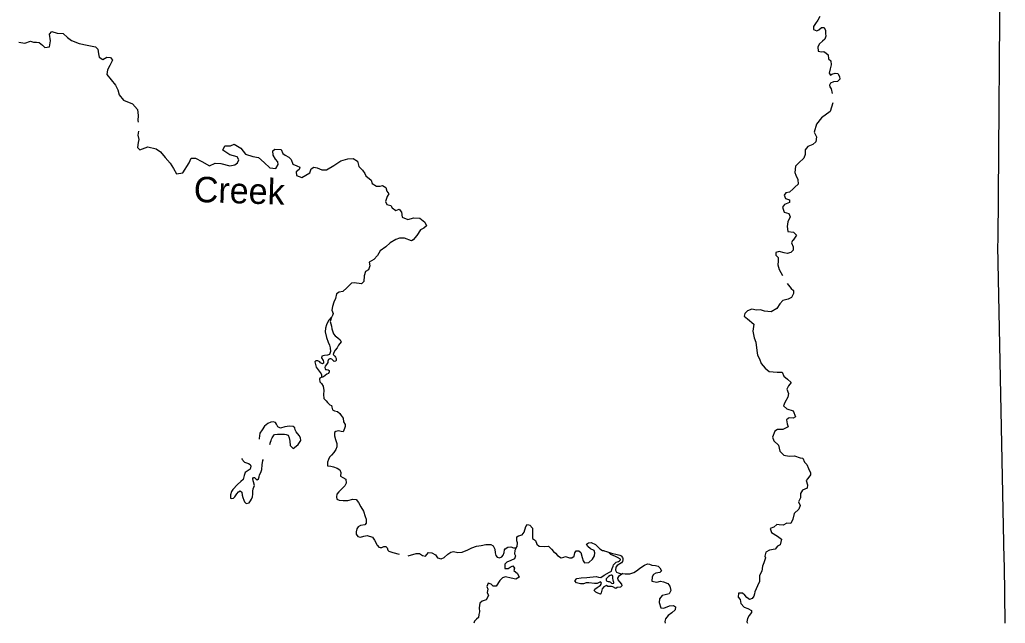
# Model space of a CAD drawing. Extents: x -492261 to -432772, y 1441225 to 1452922.
# Drawn here: x -459662.3 to -459457.9, y 1451554.7 to 1451679.8 of the extents above; entities that cross this region are included whole.
import ezdxf

# ---------------------------------------------------------------- set-up
doc = ezdxf.new("R2010")
doc.units = 0
doc.layers.add('Default', color=7, linetype='Continuous')

msp = doc.modelspace()

# ---------------------------------------------------------------- linework, layer by layer
at = {"layer": 'Default'}
for points in [[(-459457.93, 1451554.74), (-459458.06, 1451566.69), (-459458.15, 1451568.06), (-459459.48, 1451632.91), (-459459.37, 1451634.11), (-459458.89, 1451698.33), (-459458.81, 1451699.68), (-459458.3, 1451765.23), (-459457.92, 1451832.41), (-459458.17, 1451883.95)], [(-459496.34, 1451680.48), (-459496.75, 1451679.69), (-459497.29, 1451679.04), (-459497.69, 1451678.39), (-459497.7, 1451677.75), (-459497, 1451677.53), (-459496.56, 1451677.74), (-459496.04, 1451678.18), (-459495.46, 1451678.17), (-459495.16, 1451677.61), (-459495.22, 1451676.96), (-459495.13, 1451676.38), (-459495.35, 1451675.81), (-459495.81, 1451675.36), (-459496.41, 1451674.78), (-459496.79, 1451674.2), (-459496.7, 1451673.31), (-459496.02, 1451673.17), (-459495.52, 1451673.21), (-459495.05, 1451672.87), (-459494.61, 1451672.52), (-459494.58, 1451671.73), (-459494.07, 1451671.31), (-459494.05, 1451670.47), (-459494.25, 1451669.63), (-459494.41, 1451668.76), (-459494.14, 1451668.29), (-459493.86, 1451668.5), (-459493.2, 1451668.75), (-459492.66, 1451668.66), (-459492.26, 1451668.07), (-459492.22, 1451667.49), (-459492.68, 1451666.98), (-459493.51, 1451666.91), (-459494.18, 1451666.66), (-459494.37, 1451666.24), (-459494.31, 1451665.88), (-459494.05, 1451665.51), (-459493.83, 1451664.49)], [(-459662.43, 1451675.18), (-459661.19, 1451674.96), (-459659.99, 1451675.36), (-459659.39, 1451675.18), (-459658.76, 1451675.14), (-459658.22, 1451675.06), (-459657.53, 1451674.51), (-459657.02, 1451674.05), (-459656.07, 1451674.22), (-459655.88, 1451675.42), (-459656.06, 1451676.8), (-459655.58, 1451677.39), (-459654.46, 1451677.03), (-459653.23, 1451676.93), (-459652.38, 1451676.16), (-459651.49, 1451675.5), (-459649.93, 1451674.85), (-459648.26, 1451674.54), (-459646.56, 1451674.22), (-459646.06, 1451673.7), (-459645.95, 1451672.77), (-459645.81, 1451672.03), (-459645.02, 1451671.54), (-459644.16, 1451672.07), (-459643.44, 1451671.96), (-459643, 1451671.43), (-459643.59, 1451670.32), (-459644.06, 1451669.44), (-459644.19, 1451668.45), (-459643.28, 1451667.32), (-459642.43, 1451666.24), (-459641.9, 1451665.3), (-459641.62, 1451664.23), (-459640.75, 1451663.17), (-459638.89, 1451662.36), (-459637.85, 1451661.21), (-459637.69, 1451659.96), (-459637.77, 1451658.96), (-459637.73, 1451658.58)], [(-459493.7, 1451662.61), (-459494.21, 1451660.81), (-459496.01, 1451659.45), (-459497.04, 1451658.14), (-459497.51, 1451656.52), (-459497.03, 1451655.57), (-459497.2, 1451654.52), (-459497.81, 1451653.94), (-459498.83, 1451653.54), (-459499.42, 1451652.85), (-459499.41, 1451651.89), (-459499.7, 1451651.15), (-459500.74, 1451650.16), (-459501.4, 1451649.46), (-459501.56, 1451648.18), (-459501.35, 1451647.58), (-459500.95, 1451646.73), (-459500.85, 1451645.7), (-459501.58, 1451645.14), (-459501.9, 1451644.79), (-459502.64, 1451644.06), (-459503.41, 1451643.91), (-459503.74, 1451643.48), (-459503.47, 1451642.75), (-459502.66, 1451642.49), (-459502.66, 1451641.95), (-459503.7, 1451641.54), (-459504.1, 1451640.97), (-459503.77, 1451639.92), (-459502.8, 1451639.64), (-459502.54, 1451638.98), (-459502.97, 1451637.91), (-459503.12, 1451636.99), (-459503.02, 1451635.92), (-459501.83, 1451635.78), (-459501.24, 1451635.15), (-459501.88, 1451634.12), (-459502.01, 1451634.04), (-459502.22, 1451633.59), (-459501.9, 1451632.73), (-459501.88, 1451632.09), (-459502.36, 1451631.56), (-459503.13, 1451631.39), (-459503.73, 1451631.48), (-459504.77, 1451631.81), (-459505.49, 1451631.55), (-459505.52, 1451631.01), (-459505, 1451630.55), (-459505.04, 1451629.81), (-459505.08, 1451629), (-459504.77, 1451628.03), (-459504.12, 1451626.79)], [(-459637.66, 1451656.7), (-459637.79, 1451655.92), (-459637.55, 1451655.01), (-459637.7, 1451654.34), (-459637.81, 1451653.3), (-459637.33, 1451652.86), (-459635.68, 1451653.44), (-459634, 1451653.06), (-459633.09, 1451652.44), (-459632.12, 1451651.26), (-459631.08, 1451650.06), (-459630.39, 1451648.99), (-459629.76, 1451647.89), (-459628.43, 1451648.06), (-459627.1, 1451650.18), (-459626.69, 1451651.1), (-459625.78, 1451651.13), (-459624.5, 1451650.46), (-459622.88, 1451649.54), (-459621.72, 1451650.08), (-459620.55, 1451650), (-459618.68, 1451649.51), (-459617.69, 1451649.76), (-459617.08, 1451650.16), (-459616.84, 1451650.8), (-459617.15, 1451651.37), (-459618.7, 1451651.83), (-459620.13, 1451652.81), (-459619.76, 1451653.66), (-459618.57, 1451653.68), (-459617.77, 1451654.01), (-459616.42, 1451653.2), (-459615.43, 1451651.98), (-459613.95, 1451651.46), (-459612.78, 1451651.26), (-459611.55, 1451650.24), (-459610.41, 1451649.11), (-459609.13, 1451648.96), (-459608.65, 1451649.84), (-459608.76, 1451650.37)], [(-459608.76, 1451650.37), (-459609.22, 1451650.94), (-459609.73, 1451651.74), (-459609.8, 1451652.62), (-459609.36, 1451653.01), (-459608.08, 1451652.94), (-459607.73, 1451652.11), (-459607.22, 1451651.74), (-459606.49, 1451651.33), (-459606, 1451650.82), (-459605.63, 1451649.86), (-459604.82, 1451649.56), (-459604.16, 1451649.28), (-459604.33, 1451648.77), (-459604.94, 1451648.27), (-459604.84, 1451647.56), (-459603.76, 1451647.09), (-459602.11, 1451648.1), (-459601.81, 1451648.89), (-459601.28, 1451649.23), (-459600.59, 1451649.13), (-459599.61, 1451648.72), (-459598.62, 1451648.69), (-459597.16, 1451649.61), (-459595.67, 1451650.54), (-459594.25, 1451650.96), (-459593.15, 1451651.04), (-459592.24, 1451650.48), (-459591.93, 1451649.42), (-459591.19, 1451648.61), (-459590.69, 1451647.92), (-459590.5, 1451647.45), (-459589.42, 1451646.59), (-459589.16, 1451645.86), (-459588.26, 1451645.34), (-459587.52, 1451645.32), (-459587.07, 1451645.47), (-459586.33, 1451645.02), (-459586.17, 1451644.31), (-459585.72, 1451643.76), (-459586.06, 1451643.16), (-459586.44, 1451642.12), (-459586.14, 1451641.54), (-459585.3, 1451641.34), (-459585.07, 1451640.8), (-459584.3, 1451640.25), (-459583.57, 1451640.52), (-459583.09, 1451639.94), (-459582.98, 1451638.93), (-459581.81, 1451638.39), (-459580.55, 1451638.77), (-459579.27, 1451638.66), (-459578.29, 1451637.84), (-459577.92, 1451637.11), (-459578.47, 1451636.63), (-459579.18, 1451636.24), (-459579.95, 1451635.09), (-459580.65, 1451634.23), (-459581.05, 1451633.98), (-459582.47, 1451634.57), (-459583.52, 1451634.54), (-459584.31, 1451634.28), (-459585.44, 1451633.58), (-459586.37, 1451632.73), (-459587.51, 1451631.95), (-459588.1, 1451630.94), (-459588.86, 1451630.15), (-459589.8, 1451629.55), (-459589.67, 1451628.78), (-459589.92, 1451627.98), (-459590.54, 1451627.64), (-459590.83, 1451626.76), (-459590.88, 1451625.59), (-459591.42, 1451625.09), (-459592.92, 1451625.29), (-459593.48, 1451625.2), (-459594.43, 1451624.25), (-459595.23, 1451623.51), (-459596.05, 1451623.38), (-459596.57, 1451623), (-459596.81, 1451622.03), (-459597.1, 1451621.28), (-459597.39, 1451620.35), (-459597.53, 1451619.62), (-459597.28, 1451618.91), (-459597.38, 1451618.5), (-459597.57, 1451618.22), (-459597.59, 1451618.18)], [(-459503.16, 1451625.14), (-459502.32, 1451624.09), (-459501.85, 1451623.68), (-459501.83, 1451623.05), (-459502.23, 1451622.23), (-459502.91, 1451621.88), (-459504.05, 1451621.63), (-459504.63, 1451620.96), (-459505.29, 1451619.97), (-459506.48, 1451619.3), (-459507.83, 1451619.41), (-459508.7, 1451619.68), (-459509.51, 1451619.61), (-459510.47, 1451619.81), (-459511.34, 1451619.48), (-459511.93, 1451618.96), (-459512.06, 1451618.38), (-459511.36, 1451617.82), (-459510.08, 1451616.72), (-459510.24, 1451615.29), (-459510, 1451613.88), (-459509.65, 1451612.97), (-459509.42, 1451611.28), (-459509.26, 1451610.27), (-459508.9, 1451609.56), (-459508.52, 1451608.54), (-459507.72, 1451607.58), (-459506.89, 1451606.91), (-459505.21, 1451606.75), (-459504.18, 1451606.75), (-459503.86, 1451605.92), (-459503.06, 1451605.32), (-459502.33, 1451604.62), (-459502.85, 1451603.97), (-459503.19, 1451603.26), (-459502.88, 1451602.36), (-459503.03, 1451601.59), (-459503.61, 1451600.48), (-459503.93, 1451599.81), (-459503.2, 1451599.18), (-459501.89, 1451598.75), (-459501.39, 1451597.54), (-459501.89, 1451597.23), (-459502.71, 1451597.33)], [(-459597.59, 1451618.18), (-459598.17, 1451617.57), (-459598.47, 1451617.1), (-459598.67, 1451616.57), (-459598.89, 1451615.92), (-459598.96, 1451615.12), (-459598.62, 1451613.93), (-459598.31, 1451613.01), (-459598.05, 1451612.34), (-459597.91, 1451611.82), (-459597.85, 1451611.08), (-459598, 1451610.46), (-459598.41, 1451610.3), (-459599.07, 1451610.21), (-459599.63, 1451610.06), (-459599.69, 1451609.73), (-459599.37, 1451609.19), (-459599.28, 1451608.91), (-459599.26, 1451608.61), (-459599.48, 1451608.52), (-459599.88, 1451608.73), (-459600.04, 1451608.9), (-459600.47, 1451609.15), (-459600.89, 1451609.14), (-459601.09, 1451608.91), (-459600.78, 1451607.78), (-459600.36, 1451607.28), (-459599.93, 1451606.74), (-459599.75, 1451606.41), (-459599.69, 1451606.25), (-459599.66, 1451606.07), (-459599.67, 1451605.76)], [(-459597.59, 1451618.18), (-459597.91, 1451617.29), (-459597.61, 1451616.32), (-459597.57, 1451615.75), (-459597.23, 1451614.74), (-459596.88, 1451614.31), (-459596.3, 1451613.86), (-459595.83, 1451613.48), (-459595.61, 1451613.08), (-459595.86, 1451612.73), (-459596.16, 1451612.37), (-459596.42, 1451611.83), (-459596.82, 1451611.32), (-459597.15, 1451610.84), (-459597.27, 1451610.44), (-459596.94, 1451610.1), (-459596.8, 1451609.86), (-459596.66, 1451609.64), (-459596.62, 1451609.28), (-459596.73, 1451609.05), (-459597.05, 1451608.99), (-459597.42, 1451609.33), (-459597.55, 1451609.46), (-459597.74, 1451609.55), (-459597.95, 1451609.53), (-459598.24, 1451609.39), (-459598.34, 1451609.05), (-459598.37, 1451608.76), (-459598.63, 1451608.35), (-459598.9, 1451608.01), (-459599, 1451607.74), (-459598.94, 1451607.45), (-459598.87, 1451607.34), (-459598.63, 1451607.3), (-459598.33, 1451607.26), (-459598.1, 1451607.15), (-459598.07, 1451606.82), (-459598.26, 1451606.47), (-459598.57, 1451606.37), (-459599.3, 1451605.84), (-459599.51, 1451605.77), (-459599.67, 1451605.76)], [(-459599.67, 1451605.76), (-459599.75, 1451605.69), (-459600.01, 1451605.54), (-459600.12, 1451605.33), (-459600.01, 1451604.75), (-459599.71, 1451604.44), (-459599.36, 1451603.9), (-459599.2, 1451602.97), (-459599.26, 1451602.15), (-459599.18, 1451601.34), (-459598.7, 1451600.81), (-459598.43, 1451600.46), (-459597.93, 1451599.99), (-459597.64, 1451599.87), (-459597.52, 1451599.49), (-459597.43, 1451598.97), (-459596.98, 1451598.76), (-459596.39, 1451598.62), (-459595.9, 1451598.24), (-459595.6, 1451597.79), (-459595.18, 1451597.23), (-459595.11, 1451596.5), (-459594.77, 1451595.92), (-459594.79, 1451595.5), (-459594.89, 1451595.09), (-459595.22, 1451594.4), (-459595.64, 1451594.45), (-459596.15, 1451594.59), (-459596.75, 1451594.5), (-459596.97, 1451594.29), (-459596.99, 1451593.55), (-459596.78, 1451592.85), (-459596.51, 1451592.01), (-459596.53, 1451591.33), (-459596.74, 1451590.77), (-459597.16, 1451590.16), (-459597.58, 1451589.61), (-459598.02, 1451589.13), (-459598.24, 1451588.66), (-459598.42, 1451588.15), (-459598.44, 1451587.36), (-459597.72, 1451587.29), (-459597.23, 1451587.15), (-459596.47, 1451586.87), (-459595.9, 1451586.53), (-459595.71, 1451585.96), (-459595.75, 1451585.21), (-459595.28, 1451584.96), (-459594.61, 1451584.6), (-459594.54, 1451583.76), (-459594.87, 1451583.21), (-459595.54, 1451582.55), (-459596.12, 1451582.01), (-459596.48, 1451581.52), (-459596.6, 1451580.94), (-459596.49, 1451580.47), (-459596.05, 1451580.28), (-459595.17, 1451580.2), (-459594.22, 1451580.18), (-459593.18, 1451580.48), (-459592.51, 1451580.37), (-459592, 1451579.76), (-459591.56, 1451578.89), (-459590.97, 1451577.96), (-459590.63, 1451576.9), (-459590.45, 1451576.3), (-459590.46, 1451575.51), (-459590.73, 1451575.17), (-459591.6, 1451574.97), (-459592.11, 1451574.7), (-459592.38, 1451574.28), (-459592.52, 1451573.69), (-459592.48, 1451573.19), (-459592.13, 1451572.69), (-459591.57, 1451572.57), (-459590.94, 1451572.76), (-459590.22, 1451572.94), (-459589.11, 1451572.58), (-459588.7, 1451571.94), (-459588.16, 1451570.94), (-459588.1, 1451570.86), (-459587.81, 1451570.54), (-459587.55, 1451570.41), (-459587.17, 1451570.45), (-459586.76, 1451570.63), (-459586.37, 1451570.63), (-459586.09, 1451570.35), (-459585.95, 1451569.87), (-459585.75, 1451569.69), (-459584.91, 1451569.39), (-459583.61, 1451569.05)], [(-459609.89, 1451593.16), (-459609.65, 1451593.56), (-459609.44, 1451593.84), (-459608.81, 1451593.95), (-459608.15, 1451593.96), (-459607.39, 1451593.93), (-459606.98, 1451593.88), (-459606.57, 1451593.72), (-459606.42, 1451593.16), (-459606.28, 1451592.47), (-459606.17, 1451591.55), (-459605.59, 1451590.97), (-459605.3, 1451591.17), (-459604.55, 1451591.81), (-459603.98, 1451592.6), (-459604.02, 1451593.17), (-459604.33, 1451593.67), (-459604.96, 1451594.39), (-459605.17, 1451594.81), (-459605.23, 1451595.26), (-459605.58, 1451595.54), (-459606.35, 1451595.61), (-459607.29, 1451595.47), (-459608.21, 1451595.2), (-459608.74, 1451595.42), (-459609, 1451596), (-459609.23, 1451596.38), (-459609.68, 1451596.46), (-459610.21, 1451596.42), (-459610.81, 1451596.12), (-459611.48, 1451595.57), (-459611.99, 1451594.81), (-459612.5, 1451594.15), (-459612.61, 1451593.04), (-459612.63, 1451592.87)], [(-459502.71, 1451597.33), (-459502.92, 1451597.19), (-459503.3, 1451596.9), (-459503.14, 1451596.04), (-459502.94, 1451595.44), (-459504.03, 1451594.91), (-459505.17, 1451594.9), (-459505.7, 1451594.55), (-459506.16, 1451593.32), (-459505.93, 1451592.54), (-459504.92, 1451591.66), (-459504.63, 1451590.42), (-459503.82, 1451589.6), (-459502.74, 1451589.36), (-459501.59, 1451589.47), (-459500.44, 1451589.04), (-459499.86, 1451588.94), (-459499.52, 1451588.12), (-459499.03, 1451587.65), (-459498.75, 1451586.82), (-459498.31, 1451585.95), (-459498.29, 1451585.5), (-459498.87, 1451584.72), (-459499.19, 1451584.34), (-459498.96, 1451583.4), (-459499, 1451582.77), (-459499.93, 1451582.3), (-459500.37, 1451581.66), (-459500.41, 1451580.75), (-459500.81, 1451579.93), (-459500.48, 1451579.18), (-459500.72, 1451578.36), (-459501.66, 1451577.51), (-459501.97, 1451576.31), (-459502.36, 1451575.43), (-459503.19, 1451575.49), (-459503.96, 1451575.07), (-459504.77, 1451575.14), (-459505.3, 1451575.19), (-459505.92, 1451574.64), (-459506.64, 1451574.41), (-459506.4, 1451573.55), (-459505.15, 1451572.77), (-459504.33, 1451572.16), (-459504.56, 1451570.98), (-459505.17, 1451570.74), (-459505.6, 1451570.07), (-459506.81, 1451569.86), (-459507.54, 1451569.51), (-459507.77, 1451568.62), (-459507.65, 1451568.28), (-459507.99, 1451567.25), (-459508.25, 1451566.59), (-459508.41, 1451565.52), (-459508.91, 1451564.67), (-459508.9, 1451563.37), (-459509.29, 1451562.49), (-459509.87, 1451561.23), (-459509.89, 1451560.86), (-459510.07, 1451560.33), (-459510.41, 1451559.85), (-459510.93, 1451559.65), (-459511.52, 1451560.05), (-459511.89, 1451560.57), (-459512.39, 1451560.99), (-459513.26, 1451561.01), (-459513.31, 1451560.13), (-459512.9, 1451559.66), (-459512.74, 1451558.82), (-459512.08, 1451558.09), (-459511.3, 1451557.78), (-459510.55, 1451557.42), (-459510.53, 1451556.95), (-459510.99, 1451556.35), (-459511.36, 1451555.74), (-459511.47, 1451555.04), (-459511.34, 1451554.75), (-459511.34, 1451554.74)], [(-459610.41, 1451591.78), (-459610.24, 1451592.27), (-459610.11, 1451592.62), (-459610.03, 1451592.88), (-459609.89, 1451593.16)], [(-459616.13, 1451588.89), (-459616.17, 1451588.76), (-459615.63, 1451588.13), (-459614.82, 1451587.88), (-459614.49, 1451587.62), (-459614.32, 1451587.27), (-459614.47, 1451586.69), (-459614.87, 1451586.4), (-459615.5, 1451585.97), (-459615.71, 1451585.35), (-459615.96, 1451584.54), (-459616.41, 1451584.09), (-459617.13, 1451583.48), (-459618.09, 1451582.47), (-459618.35, 1451582.03), (-459618.55, 1451581.34), (-459618.53, 1451580.69), (-459618.37, 1451580.61), (-459617.95, 1451580.67), (-459617.65, 1451580.94), (-459617.21, 1451581.55), (-459616.87, 1451581.98), (-459616.57, 1451582.19), (-459616.23, 1451581.92), (-459616.16, 1451581.32), (-459616.01, 1451580.81), (-459615.81, 1451580.23), (-459615.64, 1451579.91), (-459615.29, 1451579.59), (-459614.71, 1451579.69), (-459614.44, 1451580.1), (-459614.22, 1451580.43), (-459614.01, 1451580.91), (-459613.93, 1451581.51), (-459613.91, 1451582.09), (-459613.86, 1451582.59), (-459613.58, 1451583.31), (-459613.79, 1451584.07), (-459613.87, 1451584.29), (-459613.93, 1451584.72), (-459613.78, 1451584.98), (-459613.55, 1451584.93), (-459613.26, 1451584.6), (-459613.05, 1451584.47), (-459612.74, 1451584.68), (-459612.58, 1451585.12), (-459612.54, 1451585.48), (-459612.26, 1451585.98), (-459612.04, 1451586.6), (-459611.96, 1451587.55), (-459611.84, 1451588.46), (-459611.73, 1451588.71)], [(-459579.4, 1451569.17), (-459578.72, 1451568.78), (-459578.14, 1451568.68), (-459577.88, 1451568.98), (-459577.48, 1451569.4), (-459576.83, 1451569.37), (-459576.08, 1451568.91), (-459575.64, 1451568.3), (-459574.9, 1451568.09), (-459574.27, 1451568.37), (-459573.49, 1451569.04), (-459572.89, 1451569.46), (-459572.35, 1451569.62), (-459571.44, 1451569.44), (-459570.49, 1451569.51), (-459569.37, 1451569.94), (-459568.53, 1451570.37), (-459567.56, 1451570.74), (-459566.6, 1451570.89), (-459565.65, 1451571.09), (-459564.57, 1451571.06), (-459564.12, 1451570.76), (-459563.73, 1451570.09), (-459563.71, 1451569.33), (-459563.55, 1451568.79), (-459563.26, 1451568.43), (-459562.76, 1451568.28), (-459562.28, 1451568.53), (-459562.01, 1451568.88), (-459561.85, 1451569.41), (-459561.74, 1451569.95), (-459561.6, 1451570.17), (-459561.03, 1451570.48), (-459560.41, 1451570.56), (-459559.85, 1451570.34), (-459559.35, 1451570.37), (-459559.11, 1451570.67), (-459559.04, 1451571.39), (-459559.18, 1451571.84), (-459559.21, 1451572.64), (-459558.85, 1451572.85), (-459558.09, 1451573.06), (-459557.64, 1451573.64), (-459557.34, 1451574.77), (-459556.95, 1451575.18), (-459556.46, 1451575.05), (-459555.94, 1451574.42), (-459555.93, 1451573.32), (-459555.93, 1451572.34), (-459555.31, 1451571.9), (-459555.04, 1451571.13), (-459554.53, 1451570.73), (-459553.5, 1451570.68), (-459552.59, 1451570.7), (-459552.03, 1451570.11), (-459551.61, 1451569.59), (-459551.14, 1451569.29), (-459550.78, 1451568.77), (-459550, 1451568.32), (-459549.42, 1451568.46), (-459549.08, 1451568.6), (-459548.27, 1451568.3), (-459547.77, 1451568.27), (-459547.29, 1451568.65), (-459547.18, 1451569.37), (-459546.89, 1451569.76), (-459546.35, 1451569.74), (-459545.92, 1451569.41), (-459545.63, 1451568.34), (-459545.45, 1451567.71), (-459545.18, 1451567.29), (-459544.24, 1451567.33), (-459543.49, 1451568.03), (-459543.08, 1451568.72), (-459543.05, 1451569.34), (-459543.16, 1451569.81), (-459543.89, 1451570.18), (-459544.5, 1451570.64), (-459544.75, 1451571.14), (-459544.35, 1451571.44), (-459543.75, 1451571.51), (-459542.87, 1451571.06), (-459541.99, 1451570.15), (-459541.43, 1451569.85), (-459541.18, 1451569.82), (-459541.06, 1451569.78), (-459540.63, 1451569.63), (-459540.21, 1451569.48)], [(-459581.75, 1451568.74), (-459580.05, 1451569.19), (-459579.4, 1451569.17)], [(-459559.35, 1451570.37), (-459559.6, 1451569.8), (-459559.66, 1451569.12), (-459559.5, 1451568.7), (-459559.7, 1451568.11), (-459560.44, 1451567.73), (-459561.23, 1451567.41), (-459561.67, 1451566.99), (-459561.66, 1451566.09), (-459561.02, 1451566.1), (-459560.55, 1451566.36), (-459560.04, 1451566.66), (-459559.67, 1451566.18), (-459559.83, 1451565.65), (-459559.03, 1451565.07), (-459558.7, 1451564.29), (-459559.38, 1451563.87), (-459560.38, 1451564.07), (-459561.52, 1451564.34), (-459562.16, 1451564.13), (-459562.73, 1451563.59), (-459563.48, 1451562.46), (-459564.08, 1451562.41), (-459564.51, 1451562.87), (-459565.1, 1451563.06), (-459565.4, 1451562.35), (-459565.21, 1451561.79), (-459565.36, 1451561.11), (-459565.06, 1451560.48), (-459565.53, 1451559.63), (-459566.38, 1451559.34), (-459566.85, 1451558.91), (-459567, 1451557.96), (-459566.93, 1451557.12), (-459567.09, 1451556.59), (-459567.12, 1451555.93), (-459567.56, 1451555.61), (-459567.99, 1451555.16), (-459568.13, 1451554.74)], [(-459540.21, 1451569.48), (-459539.54, 1451569.24), (-459538.36, 1451568.96), (-459537.85, 1451568.86), (-459537.54, 1451568.69), (-459537.28, 1451568.4), (-459537.2, 1451568.17), (-459537.23, 1451567.88), (-459537.3, 1451567.54), (-459537.49, 1451567.29), (-459538.37, 1451566.68), (-459538.63, 1451566.34), (-459538.71, 1451565.73), (-459538.51, 1451565.31), (-459538.21, 1451565.18), (-459537.56, 1451565.01), (-459537.18, 1451565.03), (-459538.08, 1451564.43), (-459538.34, 1451564.12), (-459538.27, 1451563.71), (-459537.87, 1451563.3), (-459537.46, 1451562.82), (-459537.42, 1451562.48), (-459537.67, 1451562.22), (-459538.37, 1451562.18), (-459538.68, 1451561.98), (-459539.3, 1451562.28), (-459539.55, 1451562.34), (-459540.34, 1451562.36), (-459540.59, 1451562.54), (-459541.14, 1451562.29), (-459541.48, 1451561.9), (-459541.69, 1451561.06), (-459541.75, 1451560.85), (-459541.85, 1451560.78), (-459542.39, 1451560.96), (-459542.83, 1451561.2), (-459543.14, 1451561.54), (-459543.01, 1451561.81), (-459542.52, 1451562.15), (-459542.11, 1451562.42), (-459541.81, 1451562.63), (-459541.66, 1451562.98), (-459541.68, 1451563.18), (-459541.86, 1451563.33), (-459542.14, 1451563.22), (-459542.56, 1451562.96), (-459543.12, 1451562.95), (-459544.23, 1451563.15), (-459544.79, 1451563.14), (-459545.35, 1451562.94), (-459546, 1451562.92), (-459546.79, 1451563.13), (-459547.16, 1451563.55), (-459546.73, 1451564.05), (-459545.84, 1451564.18), (-459544.69, 1451564.23), (-459542.72, 1451564.46), (-459542.25, 1451564.32), (-459541.8, 1451564.2), (-459541.11, 1451564.73), (-459539.95, 1451565.33), (-459539.57, 1451565.55), (-459539.49, 1451565.88), (-459539.43, 1451566.08), (-459539.24, 1451566.56), (-459539.13, 1451566.84), (-459538.89, 1451567.14), (-459538.58, 1451567.39), (-459538.14, 1451567.55), (-459537.88, 1451567.67), (-459537.67, 1451567.9), (-459537.72, 1451568.05), (-459538.31, 1451568.35), (-459538.76, 1451568.56), (-459539.2, 1451568.76), (-459539.7, 1451569.01), (-459540.21, 1451569.48)], [(-459537.18, 1451565.03), (-459536.7, 1451564.97), (-459535.79, 1451565), (-459534.92, 1451565.28), (-459534.4, 1451565.63), (-459533.77, 1451566.11), (-459533.27, 1451566.45), (-459532.72, 1451566.75), (-459532.07, 1451567.03), (-459531.67, 1451566.99), (-459531.2, 1451566.76), (-459530.44, 1451566.71), (-459529.89, 1451566.59), (-459529.53, 1451566.21), (-459529.2, 1451565.59), (-459529.55, 1451565.24), (-459530.35, 1451565.14), (-459530.84, 1451564.85), (-459531.13, 1451564.37), (-459531.17, 1451563.45), (-459530.14, 1451563.28), (-459529.39, 1451563.5), (-459528.81, 1451563.36), (-459527.87, 1451563), (-459527.44, 1451562.42), (-459527.26, 1451561.53), (-459527.58, 1451560.81), (-459528.44, 1451560.64), (-459529.09, 1451560.47), (-459529.62, 1451559.8), (-459529.68, 1451559.03), (-459529.35, 1451557.92), (-459528.7, 1451557.85), (-459527.56, 1451558.36), (-459526.7, 1451558.43), (-459526.26, 1451558.12), (-459526.36, 1451557.53), (-459527.05, 1451556.91), (-459527.81, 1451556.33), (-459528.4, 1451555.66), (-459528.53, 1451555.11), (-459528.47, 1451554.74)], [(-459539.82, 1451564.62), (-459540.2, 1451564.4), (-459540.41, 1451564.25), (-459540.6, 1451564.05), (-459540.64, 1451563.92), (-459540.67, 1451563.67), (-459540.62, 1451563.53), (-459540.44, 1451563.44), (-459540.28, 1451563.4), (-459540.07, 1451563.38), (-459539.74, 1451563.23), (-459539.58, 1451563.08), (-459539.28, 1451562.97), (-459539.1, 1451563.07), (-459539.09, 1451563.2), (-459539.12, 1451563.43), (-459539.21, 1451563.77), (-459539.27, 1451564), (-459539.27, 1451564.28), (-459539.28, 1451564.45), (-459539.33, 1451564.65), (-459539.52, 1451564.74), (-459539.62, 1451564.7), (-459539.82, 1451564.62)]]:
    msp.add_lwpolyline(points, dxfattribs=at)

# ---------------------------------------------------------------- texts
msp.add_text('Creek', height=5.28, rotation=358.2424, dxfattribs=at).set_placement((-459626.23, 1451642.05))

doc.saveas('drawing.dxf')
